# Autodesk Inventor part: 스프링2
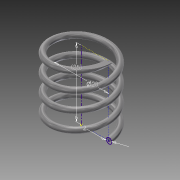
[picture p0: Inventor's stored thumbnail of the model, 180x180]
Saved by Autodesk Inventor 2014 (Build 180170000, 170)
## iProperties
Created: 2016-07
Part Number: 스프링2
Material: 스테인레스 스틸
Document SubType Name: Modeling
Designer: owner
Density: 8.08 g/cm^3
Appearance: 반연마
Author: owner
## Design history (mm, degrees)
sketch "스케치1"
  geometry: L1 (-10, 0)-(0, 0); L2 (0, 0)-(0, 19.5); L3 (0, 19.5)-(-10, 19.5); L4 (-10, 19.5)-(-10, 0); C1 r 1 at (-10, 0); 1 further point
  constraints: 8 end point, 2 coincident, 2 parallel, 1 centre point, 1 horizontal, 1 perpendicular
  dimensions: "d0" = 2 diameter of C1; "d1" = 19.5 distance of L1.end L2.end (derived); "d2" = 20 diameter of L4 L2
feature "코일1" sketch "스케치1" pitch "d3" = 10; turns "d5" = 4; dims "d4" = 19.5 (= d1), "d6" = 0, angle "d7" = 90 deg, angle "d8" = 90 deg, "d9" = 0, "d10" = 0
node "작업 평면1"
sketch "스케치2"
  geometry: L1 (0, 0)-(2, 0) reference; 1 further point
  constraints: 1 horizontal alignment
extrude "돌출1" cut sketch "스케치2" distance "d11" = 10; taper "d12" = 0 deg
node "작업 평면2"
sketch "스케치3"
  geometry: L1 (0, 0)-(-2, 0) reference; 1 further point
  constraints: 1 horizontal alignment
extrude "돌출2" cut sketch "스케치3" distance "d13" = 10; taper "d14" = 0 deg
node "솔리드1"
node "절단 모서리 투영1"
node "절단 모서리 투영2"
